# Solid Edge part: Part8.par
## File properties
Author: TIET
Template: Iso Metric Part.par
Last saved by: Rajat Kamboj
Revision: 4
Application: Solid Edge
Accuracy: 0.990
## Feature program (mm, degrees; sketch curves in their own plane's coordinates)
sketch for "unnamed Protrusion 1" plane through (0, 0, 0) normal (0, 1, 0) x-axis (1, 0, 0)
  circle centre (0, 0) radius 87.1438
extrude "unnamed Protrusion 1" add finite 20.9072 along -normal
sketch for "ExtrudedProtrusion_2" #1 plane through (0, -20.9072, 0) normal (0, -1, 0) x-axis (1, 0, 0)
  circle centre (0, 0) radius 29.2182
sketch for "ExtrudedProtrusion_2" #2 plane through (0, -20.9072, 0) normal (0, -1, 0) x-axis (1, 0, 0)
  circle centre (0, 0) radius 42.9092
extrude "ExtrudedProtrusion_2" add finite 29.1638 along +normal
sketch for "ExtrudedCutout_1" plane through (0, -20.9072, 0) normal (0, -1, 0) x-axis (1, 0, 0)
  circle centre (0, 63.4817) radius 6.8014
extrude "ExtrudedCutout_1" cut finite 88.7737 along -normal
pattern "unnamed Pattern 1" of "ExtrudedCutout_1"
extrude "unnamed Cutout 1" cut finite 88.7737
extrude "unnamed Cutout 2" cut finite 88.7737
extrude "unnamed Cutout 3" cut finite 88.7737
extrude "unnamed Cutout 4" cut finite 88.7737
extrude "unnamed Cutout 5" cut finite 88.7737
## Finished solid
Body 1: solid body, 13 faces, 18 edges, 0 vertices.
  Faces by surface: cylinder 9, plane 4
  Edges by curve: circle 18
Bounding box of the edges (mm): 174.288 x 50.071 x 174.288, from (-87.1438, -50.071, -87.1438) to (87.1438, 0, 87.1438).
Cylindrical faces by radius (mm): R6.8014 x6, R29.2182 x1, R42.9092 x1, R87.1438 x1
Planar faces by outward normal: +y 1, -y 3
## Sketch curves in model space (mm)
circle centre (0, -20.9072, 63.4817) radius 6.8014
circle centre (0, -20.9072, 0) radius 42.9092
circle centre (0, -20.9072, 0) radius 29.2182
circle centre (0, 0, 0) radius 87.1438
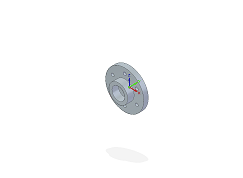
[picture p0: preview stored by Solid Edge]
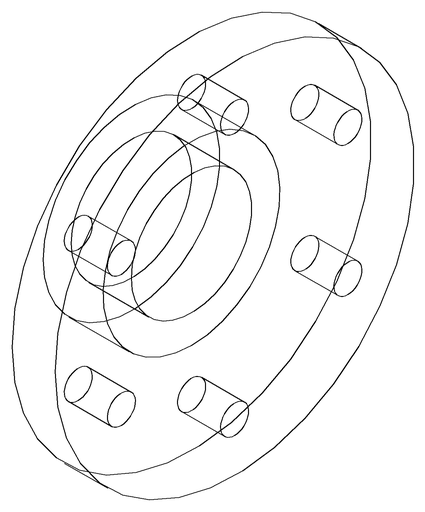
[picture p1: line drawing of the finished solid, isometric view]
